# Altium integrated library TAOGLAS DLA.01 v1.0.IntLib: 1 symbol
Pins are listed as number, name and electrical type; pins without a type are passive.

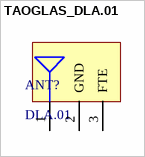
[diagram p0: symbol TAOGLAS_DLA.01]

## TAOGLAS_DLA.01
designator ANT?, comment DLA.01
DECT 1880-1930MHz Ceramic Substrate Loop Antenna; ComponentLibStatus: Created; MFG: Taoglas; Temp_High: +85C; Temp_Low: -40C
footprint TAOGLAS_DLA.01 (DECT 1880-1930MHz Ceramic Substrate Loop Antenna)
pins: 1 RF FEED, 2 GND, 3 FTE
